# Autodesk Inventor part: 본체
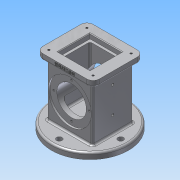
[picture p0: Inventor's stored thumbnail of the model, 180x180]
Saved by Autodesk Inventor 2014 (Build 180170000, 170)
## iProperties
Created: 2018-10
Part Number: 본체
Material: 알루미늄 6061
Document SubType Name: Modeling
Designer: Administrator
Density: 2.71 g/cm^3
Appearance: 알루미늄 - 평지
Mass: 988.221 g
Surface Area: 743.905 cm^2
Volume: 364.657 cm^3
Author: Administrator
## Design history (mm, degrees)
sketch "스케치1"
  geometry: C1 r 62.5 at (0, 0); 1 further point
  constraints: 1 centre point, 1 coincident
  dimensions: "d0" = 125 diameter of C1
extrude "돌출1" new body sketch "스케치1" distance "d1" = 10; taper "d2" = 0 deg
sketch "스케치2"
  geometry: L1 (-37, -33)-(37, -33); L2 (37, -33)-(37, 33); L3 (37, 33)-(-37, 33); L4 (-37, 33)-(-37, -33); L5 (-37, -33)-(37, 33); L6 (37, -33)-(-37, 33); 3 further points
  constraints: 12 end point, 3 midpoint, 2 parallel, 1 coincident, 1 horizontal, 1 perpendicular
  dimensions: "d3" = 74 distance of L3.end L2.end; "d4" = 66 distance of L2.end L1.end
extrude "돌출2" join sketch "스케치2" distance "d5" = 88; taper "d6" = 0 deg
sketch "스케치3"
  geometry: L1 (-46, -41)-(46, -41); L2 (46, -41)-(46, 41); L3 (46, 41)-(-46, 41); L4 (-46, 41)-(-46, -41); L5 (-46, -41)-(46, 41); L6 (46, -41)-(-46, 41); 3 further points
  constraints: 12 end point, 3 midpoint, 2 parallel, 1 coincident, 1 horizontal, 1 perpendicular
  dimensions: "d7" = 92 distance of L3.end L2.end; "d8" = 82 distance of L2.end L1.end
extrude "돌출3" join sketch "스케치3" distance "d9" = 10; taper "d10" = 0 deg
fillet "모깎기1" dims "d11" = 10
sketch "스케치4"
  geometry: L1 (-26, -26)-(26, -26); L2 (26, -26)-(26, 26); L3 (26, 26)-(-26, 26); L4 (-26, 26)-(-26, -26); L5 (-26, -26)-(26, 26); L6 (26, -26)-(-26, 26); 3 further points
  constraints: 12 end point, 3 midpoint, 2 parallel, 1 coincident, 1 horizontal, 1 perpendicular
  dimensions: "d12" = 52 distance of L3.end L2.end; "d13" = 52 distance of L2.end L1.end
extrude "돌출4" cut sketch "스케치4" distance "d14" = 8; taper "d15" = 0 deg
sketch "스케치5"
  geometry: L1 (-22, -22)-(22, -22); L2 (22, -22)-(22, 22); L3 (22, 22)-(-22, 22); L4 (-22, 22)-(-22, -22); L5 (-22, -22)-(22, 22); L6 (22, -22)-(-22, 22); 3 further points
  constraints: 12 end point, 3 midpoint, 2 parallel, 1 coincident, 1 horizontal, 1 perpendicular
  dimensions: "d16" = 44 distance of L3.end L2.end; "d17" = 44 distance of L2.end L1.end
sketch "스케치7"
  geometry: L1 (-25.5, -10)-(99.5, -10) reference; C1 r 35 at (37, 44); 2 further points
  constraints: 1 centre point, 1 midpoint, 1 vertical alignment
  dimensions: "d18" = 70 diameter of C1; "d19" = 54 distance from line of C1.centre L1
extrude "돌출5" cut sketch "스케치7" distance "d20" = 3; taper "d21" = 0 deg
extrude "돌출6" cut sketch "스케치5" distance "d22" = 74; taper "d23" = 0 deg
sketch "스케치9"
  geometry: C1 r 24 at (0, 0); 1 further point
  constraints: 1 centre point, 1 vertical alignment
  dimensions: "d24" = 54 distance of C1.centre point (0, -54); "d25" = 48 diameter of C1
extrude "돌출7" cut sketch "스케치9" stored distance "d26" = 74; taper "d27" = 0 deg
sketch "스케치11"
  geometry: C1 r 28 at (0, 0); 1 further point
  constraints: 1 centre point, 1 coincident
  dimensions: "d28" = 56 diameter of C1
extrude "돌출8" cut sketch "스케치11" distance "d29" = 18; taper "d30" = -10 deg
chamfer "모따기1" distance "d31" = 1; stored, may be unused: second distance "d32" = 2, angle "d33" = 45 deg
fillet "모깎기2" dims "d34" = 3
fillet "모깎기3" dims "d35" = 3
fillet "모깎기4" dims "d36" = 3
fillet "모깎기5" dims "d37" = 3
fillet "모깎기6" dims "d38" = 3
fillet "모깎기7" dims "d39" = 3
fillet "모깎기8" dims "d40" = 3
sketch "스케치12"
  geometry: L1 (40, -44)-(51.383, -44) reference; L2 (54.829, -47)-(54.829, -54) reference; L3 (54.829, -54)-(-54.829, -54) reference; L4 (-54.829, -54)-(-54.829, -47) reference; L5 (-51.383, -44)-(-40, -44) reference; L6 (-37, -41)-(-37, 41) reference; L7 (-40, 44)-(-43, 44) reference; L8 (-46, 47)-(-46, 54) reference; L9 (-46, 54)-(46, 54) reference; L10 (46, 54)-(46, 47) reference; L11 (43, 44)-(40, 44) reference; L12 (37, 41)-(37, -41) reference; C1 r 35 at (0, 0) reference; C2 r 24 at (0, 0) reference; A1 r 3 centre (40, -41) between (37, -41) and (40, -44) reference; A2 r 3 centre (-40, -41) between (-40, -44) and (-37, -41) reference; A3 r 3 centre (-40, 41) between (-37, 41) and (-40, 44) reference; A4 r 3 centre (-43, 47) between (-46, 47) and (-43, 44) reference; A5 r 3 centre (43, 47) between (43, 44) and (46, 47) reference; A6 r 3 centre (40, 41) between (40, 44) and (37, 41) reference; 2 further points
  constraints: 1 vertical alignment, 2 other
  dimensions: "d43" = 29 distance of C2.centre point (0, 29)
hole "구멍1" sketch "스케치12" at (0, 29) diameter "d44" = 3.242; stored, may be unused: countersink angle "d48" = 90 deg, drill point angle "d50" = 118 deg; dims "d45" = 4, "d46" = 4, "d47" = 2, "d49" = 6
sketch "스케치13"
  geometry: 2 further points
  constraints: 1 vertical alignment
  dimensions: "d55" = 50 distance of point (0, 50) point (0, 0)
hole "구멍2" sketch "스케치13" at (0, 50) diameter "d56" = 9; stored, may be unused: countersink angle "d60" = 90 deg, drill point angle "d62" = 118 deg; dims "d57" = 4, "d58" = 4, "d59" = 2, "d61" = 6
sketch "스케치14"
  geometry: L1 (95, -32.5)-(95, 92.5) reference; 3 further points
  constraints: 2 horizontal alignment
  dimensions: "d66" = 37 distance from line of L1 point (58, 30); "d67" = 43 distance of point (58, 30) point (15, 30)
hole "구멍3" sketch "스케치14" at (58, 30), (15, 30) diameter "d68" = 4.134; stored, may be unused: countersink angle "d72" = 90 deg, drill point angle "d74" = 118 deg; dims "d69" = 4, "d70" = 4, "d71" = 2, "d73" = 30
sketch "스케치15"
  geometry: L1 (-10, 0)-(-10, -7) reference; L2 (72, -7)-(0, -7) reference; L3 (0, 0)-(72, 0) reference; 2 further points
  constraints: 1 other
  dimensions: "d76" = 46 distance from line of L1 point (36, -4); "d88" = 4 distance from line of point (36, -4) L3
feature "엠보싱1" sketch "스케치15" dims "d77" = 0.5, "d78" = 0
sketch "스케치16"
  geometry: 2 further points
  dimensions: "d79" = 31 vertical distance of point (-36, 31) point (0, 0); "d80" = 36 horizontal distance of point (0, 0) point (-36, 31)
hole "구멍4" sketch "스케치16" at (-36, 31) diameter "d81" = 3.242; stored, may be unused: countersink angle "d85" = 90 deg, drill point angle "d87" = 118 deg; dims "d82" = 4, "d83" = 4, "d84" = 2, "d86" = 6
node "솔리드1"
mirror "대칭1"
pattern_circular "원형 패턴1" dims angle "d52" = 360 deg
mirror "대칭2"
pattern_circular "원형 패턴2" dims angle "d64" = 360 deg
mirror "대칭3"
mirror "대칭4"
node "절단 모서리 투영1"
